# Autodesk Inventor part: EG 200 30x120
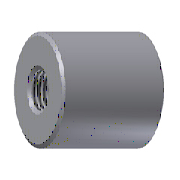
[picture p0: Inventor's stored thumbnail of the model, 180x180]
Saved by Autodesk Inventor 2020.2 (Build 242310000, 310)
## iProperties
IsCustomPart: 0
Manager: www.cadconsulting.pl
Company: Fabian Stasiak CAD Consulting
Created: 2014-02
Part Number: EG 200 30x120
Material: DIN 1.7131
Description: Locating sleeves
Document SubType Name: Modeling
Designer: F.Stasiak
Standard Revision: 1
Manufacturer: DME
Language: pl-PL
Size Designation: 30x120
Categories: <MemberInstance><Categories><Category DisplayName="Forma wtryskowa" InternalName="349578f2-f4d4-4954-8c09-8e99297a61c0" Mnemonic="MOLD"><Category DisplayName="E
Mass: 1.68626 g
Surface Area: 16.3679 cm^2
Volume: 1.68626 cm^3
Density: 7.85 g/cm^3
Appearance: Stal
Catalog Web Link: www.expertbooks.pl
Author: F.Stasiak
Subject: Zbiór ćwiczeń. Autodesk Inventor 2020. Kurs Professional
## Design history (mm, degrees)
sketch "Sketch1"
  geometry: L1 (0, -144)-(0, 24) reference; L2 (0, 0)-(15, 0); L3 (15, 0)-(15, -2.5); L4 (15, -2.5)-(14.99, -2.5); L5 (14.99, -2.5)-(14.99, -120); L6 (14.99, -120)-(12.5, -120); L7 (12.5, -120)-(12.5, -13); L8 (12.5, -13)-(6, -11); L9 (6, -11)-(0, -11); L10 (0, 0)-(0, -11); 1 further point
  constraints: 18 end point, 4 parallel, 3 perpendicular, 2 point on line, 1 coincident, 1 collinear
  dimensions: "d0" = 30 diameter of L3 L1 (= D); "d2" = 30 dimension on L5 L1 (= D_Guide); "d4" = 120 distance between parallel lines of L6 L2 (= L); "d5" = 25 diameter of L7 L1 (= d_); "d6" = 13 distance from line of L7.end L2 (= L1); "d7" = 2 distance from line of L7.end L9; "d8" = 12 diameter of L8.end L1 (= M); "d33" = 2.5 distance between parallel lines of L2 L4 (= L2)
revolve "Revolution1" sketch "Sketch1" stored, may be unused: angle "d9" = 90 deg
sketch "Sketch2"
  geometry: 1 further point
hole "Hole1" sketch "Sketch2" at (0, 0) diameter "d10" = 10.106; stored, may be unused: countersink angle "d14" = 90 deg, drill point angle "d16" = 0 deg; dims "d11" = 6, "d12" = 4, "d13" = 2, "d15" = 120 (= L)
chamfer "Chamfer1" distance "d17" = 0.5; stored, may be unused: second distance "d18" = 2, angle "d19" = 45 deg
fillet "Fillet1" dims "d30" = 0.5
body "Solid1"
other parameters: "D" = 30 [user parameter; used in 1 equation term], "L" = 120 [user parameter; used in 2 equation terms], "d_" = 25 [user parameter; used in 1 equation term], "M" = 12 [user parameter; used in 1 equation term], "L1" = 13 [user parameter; used in 1 equation term], "d22" = 0, "d31" = 0, "d32" = 0, "L2" = 2.5 [user parameter; used in 1 equation term]
